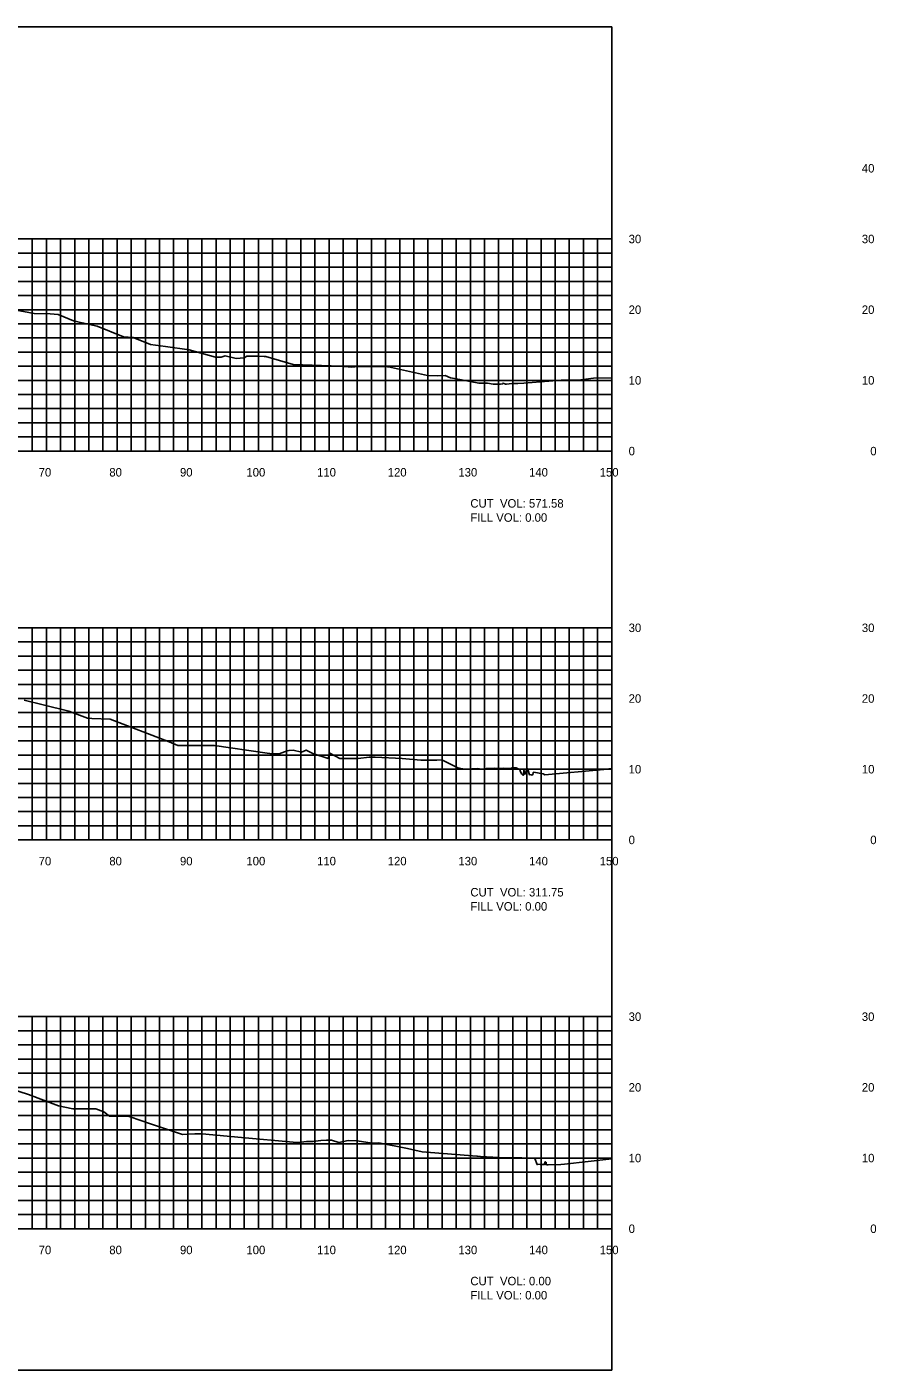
# Model space of a CAD drawing. Extents: x 1800976 to 1805104, y 250057 to 250580.
# Drawn here: x 1802358.2 to 1802478.4, y 250079.4 to 250269.4 of the extents above; entities that cross this region are included whole.
import ezdxf

# ---------------------------------------------------------------- set-up
doc = ezdxf.new("R2010")
doc.units = 0
for name, color, linetype in [('10', 7, 'Continuous'), ('31', 7, 'Continuous'), ('60', 7, 'Continuous'), ('ANNO-TXT', 7, 'Continuous'), ('Level 62', 7, 'Continuous'), ('M-ROADS', 7, 'Continuous')]:
    doc.layers.add(name, color=color, linetype=linetype)

msp = doc.modelspace()

# ---------------------------------------------------------------- linework, layer by layer
msp.add_lwpolyline([(1802141, 250079.43), (1802441, 250079.43), (1802441, 250269.43), (1802141, 250269.43)], close=True)
at = {"layer": '60'}
for p, q in [((1802441, 250209.43), (1802441, 250239.43)), ((1802441.06, 250239.43), (1802441, 250239.43)), ((1802441.06, 250229.43), (1802441, 250229.43)), ((1802441.06, 250219.43), (1802441, 250219.43)), ((1802141, 250209.43), (1802441, 250209.43)), ((1802361, 250209.37), (1802361, 250209.43)), ((1802371, 250209.37), (1802371, 250209.43)), ((1802381, 250209.37), (1802381, 250209.43)), ((1802391, 250209.37), (1802391, 250209.43)), ((1802401, 250209.37), (1802401, 250209.43)), ((1802411, 250209.37), (1802411, 250209.43)), ((1802421, 250209.37), (1802421, 250209.43)), ((1802431, 250209.37), (1802431, 250209.43)), ((1802441, 250209.37), (1802441, 250209.43)), ((1802441.06, 250209.43), (1802441, 250209.43)), ((1802441, 250154.43), (1802441, 250184.43)), ((1802441.06, 250184.43), (1802441, 250184.43)), ((1802441.06, 250174.43), (1802441, 250174.43)), ((1802441.06, 250164.43), (1802441, 250164.43)), ((1802141, 250154.43), (1802441, 250154.43)), ((1802361, 250154.37), (1802361, 250154.43)), ((1802371, 250154.37), (1802371, 250154.43)), ((1802381, 250154.37), (1802381, 250154.43)), ((1802391, 250154.37), (1802391, 250154.43)), ((1802401, 250154.37), (1802401, 250154.43)), ((1802411, 250154.37), (1802411, 250154.43)), ((1802421, 250154.37), (1802421, 250154.43)), ((1802431, 250154.37), (1802431, 250154.43)), ((1802441, 250154.37), (1802441, 250154.43)), ((1802441.06, 250154.43), (1802441, 250154.43)), ((1802441, 250099.43), (1802441, 250129.43)), ((1802441.06, 250129.43), (1802441, 250129.43)), ((1802441.06, 250119.43), (1802441, 250119.43)), ((1802441.06, 250109.43), (1802441, 250109.43)), ((1802141, 250099.43), (1802441, 250099.43)), ((1802361, 250099.37), (1802361, 250099.43)), ((1802371, 250099.37), (1802371, 250099.43)), ((1802381, 250099.37), (1802381, 250099.43)), ((1802391, 250099.37), (1802391, 250099.43)), ((1802401, 250099.37), (1802401, 250099.43)), ((1802411, 250099.37), (1802411, 250099.43)), ((1802421, 250099.37), (1802421, 250099.43)), ((1802431, 250099.37), (1802431, 250099.43)), ((1802441, 250099.37), (1802441, 250099.43)), ((1802441.06, 250099.43), (1802441, 250099.43))]:
    msp.add_line(p, q, dxfattribs=at)
at = {"layer": 'Level 62'}
for p, q in [((1802141, 250239.43), (1802441, 250239.43)), ((1802359, 250209.43), (1802359, 250239.43)), ((1802361, 250209.43), (1802361, 250239.43)), ((1802363, 250209.43), (1802363, 250239.43)), ((1802365, 250209.43), (1802365, 250239.43)), ((1802367, 250209.43), (1802367, 250239.43)), ((1802369, 250209.43), (1802369, 250239.43)), ((1802371, 250209.43), (1802371, 250239.43)), ((1802373, 250209.43), (1802373, 250239.43)), ((1802375, 250209.43), (1802375, 250239.43)), ((1802377, 250209.43), (1802377, 250239.43)), ((1802379, 250209.43), (1802379, 250239.43)), ((1802381, 250209.43), (1802381, 250239.43)), ((1802383, 250209.43), (1802383, 250239.43)), ((1802385, 250209.43), (1802385, 250239.43)), ((1802387, 250209.43), (1802387, 250239.43)), ((1802389, 250209.43), (1802389, 250239.43)), ((1802391, 250209.43), (1802391, 250239.43)), ((1802393, 250209.43), (1802393, 250239.43)), ((1802395, 250209.43), (1802395, 250239.43)), ((1802397, 250209.43), (1802397, 250239.43)), ((1802399, 250209.43), (1802399, 250239.43)), ((1802401, 250209.43), (1802401, 250239.43)), ((1802403, 250209.43), (1802403, 250239.43)), ((1802405, 250209.43), (1802405, 250239.43)), ((1802407, 250209.43), (1802407, 250239.43)), ((1802409, 250209.43), (1802409, 250239.43)), ((1802411, 250209.43), (1802411, 250239.43)), ((1802413, 250209.43), (1802413, 250239.43)), ((1802415, 250209.43), (1802415, 250239.43)), ((1802417, 250209.43), (1802417, 250239.43)), ((1802419, 250209.43), (1802419, 250239.43)), ((1802421, 250209.43), (1802421, 250239.43)), ((1802423, 250209.43), (1802423, 250239.43)), ((1802425, 250209.43), (1802425, 250239.43)), ((1802427, 250209.43), (1802427, 250239.43)), ((1802429, 250209.43), (1802429, 250239.43)), ((1802431, 250209.43), (1802431, 250239.43)), ((1802433, 250209.43), (1802433, 250239.43)), ((1802435, 250209.43), (1802435, 250239.43)), ((1802437, 250209.43), (1802437, 250239.43)), ((1802439, 250209.43), (1802439, 250239.43)), ((1802441, 250209.43), (1802441, 250239.43)), ((1802141, 250237.43), (1802441, 250237.43)), ((1802141, 250235.43), (1802441, 250235.43)), ((1802141, 250233.43), (1802441, 250233.43)), ((1802141, 250231.43), (1802441, 250231.43)), ((1802141, 250229.43), (1802441, 250229.43)), ((1802141, 250227.43), (1802441, 250227.43)), ((1802141, 250225.43), (1802441, 250225.43)), ((1802141, 250223.43), (1802441, 250223.43)), ((1802141, 250221.43), (1802441, 250221.43)), ((1802141, 250219.43), (1802441, 250219.43)), ((1802141, 250217.43), (1802441, 250217.43)), ((1802141, 250215.43), (1802441, 250215.43)), ((1802141, 250213.43), (1802441, 250213.43)), ((1802141, 250211.43), (1802441, 250211.43)), ((1802141, 250209.43), (1802441, 250209.43)), ((1802141, 250184.43), (1802441, 250184.43)), ((1802359, 250154.43), (1802359, 250184.43)), ((1802361, 250154.43), (1802361, 250184.43)), ((1802363, 250154.43), (1802363, 250184.43)), ((1802365, 250154.43), (1802365, 250184.43)), ((1802367, 250154.43), (1802367, 250184.43)), ((1802369, 250154.43), (1802369, 250184.43)), ((1802371, 250154.43), (1802371, 250184.43)), ((1802373, 250154.43), (1802373, 250184.43)), ((1802375, 250154.43), (1802375, 250184.43)), ((1802377, 250154.43), (1802377, 250184.43)), ((1802379, 250154.43), (1802379, 250184.43)), ((1802381, 250154.43), (1802381, 250184.43)), ((1802383, 250154.43), (1802383, 250184.43)), ((1802385, 250154.43), (1802385, 250184.43)), ((1802387, 250154.43), (1802387, 250184.43)), ((1802389, 250154.43), (1802389, 250184.43)), ((1802391, 250154.43), (1802391, 250184.43)), ((1802393, 250154.43), (1802393, 250184.43)), ((1802395, 250154.43), (1802395, 250184.43)), ((1802397, 250154.43), (1802397, 250184.43)), ((1802399, 250154.43), (1802399, 250184.43)), ((1802401, 250154.43), (1802401, 250184.43)), ((1802403, 250154.43), (1802403, 250184.43)), ((1802405, 250154.43), (1802405, 250184.43)), ((1802407, 250154.43), (1802407, 250184.43)), ((1802409, 250154.43), (1802409, 250184.43)), ((1802411, 250154.43), (1802411, 250184.43)), ((1802413, 250154.43), (1802413, 250184.43)), ((1802415, 250154.43), (1802415, 250184.43)), ((1802417, 250154.43), (1802417, 250184.43)), ((1802419, 250154.43), (1802419, 250184.43)), ((1802421, 250154.43), (1802421, 250184.43)), ((1802423, 250154.43), (1802423, 250184.43)), ((1802425, 250154.43), (1802425, 250184.43)), ((1802427, 250154.43), (1802427, 250184.43)), ((1802429, 250154.43), (1802429, 250184.43)), ((1802431, 250154.43), (1802431, 250184.43)), ((1802433, 250154.43), (1802433, 250184.43)), ((1802435, 250154.43), (1802435, 250184.43)), ((1802437, 250154.43), (1802437, 250184.43)), ((1802439, 250154.43), (1802439, 250184.43)), ((1802441, 250154.43), (1802441, 250184.43)), ((1802141, 250182.43), (1802441, 250182.43)), ((1802141, 250180.43), (1802441, 250180.43)), ((1802141, 250178.43), (1802441, 250178.43)), ((1802141, 250176.43), (1802441, 250176.43)), ((1802141, 250174.43), (1802441, 250174.43)), ((1802141, 250172.43), (1802441, 250172.43)), ((1802141, 250170.43), (1802441, 250170.43)), ((1802141, 250168.43), (1802441, 250168.43)), ((1802141, 250166.43), (1802441, 250166.43)), ((1802141, 250164.43), (1802441, 250164.43)), ((1802141, 250162.43), (1802441, 250162.43)), ((1802141, 250160.43), (1802441, 250160.43)), ((1802141, 250158.43), (1802441, 250158.43)), ((1802141, 250156.43), (1802441, 250156.43)), ((1802141, 250154.43), (1802441, 250154.43)), ((1802141, 250129.43), (1802441, 250129.43)), ((1802359, 250099.43), (1802359, 250129.43)), ((1802361, 250099.43), (1802361, 250129.43)), ((1802363, 250099.43), (1802363, 250129.43)), ((1802365, 250099.43), (1802365, 250129.43)), ((1802367, 250099.43), (1802367, 250129.43)), ((1802369, 250099.43), (1802369, 250129.43)), ((1802371, 250099.43), (1802371, 250129.43)), ((1802373, 250099.43), (1802373, 250129.43)), ((1802375, 250099.43), (1802375, 250129.43)), ((1802377, 250099.43), (1802377, 250129.43)), ((1802379, 250099.43), (1802379, 250129.43)), ((1802381, 250099.43), (1802381, 250129.43)), ((1802383, 250099.43), (1802383, 250129.43)), ((1802385, 250099.43), (1802385, 250129.43)), ((1802387, 250099.43), (1802387, 250129.43)), ((1802389, 250099.43), (1802389, 250129.43)), ((1802391, 250099.43), (1802391, 250129.43)), ((1802393, 250099.43), (1802393, 250129.43)), ((1802395, 250099.43), (1802395, 250129.43)), ((1802397, 250099.43), (1802397, 250129.43)), ((1802399, 250099.43), (1802399, 250129.43)), ((1802401, 250099.43), (1802401, 250129.43)), ((1802403, 250099.43), (1802403, 250129.43)), ((1802405, 250099.43), (1802405, 250129.43)), ((1802407, 250099.43), (1802407, 250129.43)), ((1802409, 250099.43), (1802409, 250129.43)), ((1802411, 250099.43), (1802411, 250129.43)), ((1802413, 250099.43), (1802413, 250129.43)), ((1802415, 250099.43), (1802415, 250129.43)), ((1802417, 250099.43), (1802417, 250129.43)), ((1802419, 250099.43), (1802419, 250129.43)), ((1802421, 250099.43), (1802421, 250129.43)), ((1802423, 250099.43), (1802423, 250129.43)), ((1802425, 250099.43), (1802425, 250129.43)), ((1802427, 250099.43), (1802427, 250129.43)), ((1802429, 250099.43), (1802429, 250129.43)), ((1802431, 250099.43), (1802431, 250129.43)), ((1802433, 250099.43), (1802433, 250129.43)), ((1802435, 250099.43), (1802435, 250129.43)), ((1802437, 250099.43), (1802437, 250129.43)), ((1802439, 250099.43), (1802439, 250129.43)), ((1802441, 250099.43), (1802441, 250129.43)), ((1802141, 250127.43), (1802441, 250127.43)), ((1802141, 250125.43), (1802441, 250125.43)), ((1802141, 250123.43), (1802441, 250123.43)), ((1802141, 250121.43), (1802441, 250121.43)), ((1802141, 250119.43), (1802441, 250119.43)), ((1802141, 250117.43), (1802441, 250117.43)), ((1802141, 250115.43), (1802441, 250115.43)), ((1802141, 250113.43), (1802441, 250113.43)), ((1802141, 250111.43), (1802441, 250111.43)), ((1802141, 250109.43), (1802441, 250109.43)), ((1802141, 250107.43), (1802441, 250107.43)), ((1802141, 250105.43), (1802441, 250105.43)), ((1802141, 250103.43), (1802441, 250103.43)), ((1802141, 250101.43), (1802441, 250101.43)), ((1802141, 250099.43), (1802441, 250099.43))]:
    msp.add_line(p, q, dxfattribs=at)
at = {"layer": 'M-ROADS'}
for points in [[(1802344.77, 250231.59), (1802359.28, 250228.9), (1802361.52, 250228.82), (1802362.66, 250228.77), (1802364.81, 250227.83), (1802366.25, 250227.53), (1802368.19, 250227.12), (1802371.89, 250225.59), (1802373.26, 250225.5), (1802375.72, 250224.51), (1802377.84, 250224.23), (1802381.19, 250223.77), (1802384.92, 250222.73), (1802385.71, 250222.73), (1802386.3, 250222.88), (1802387.87, 250222.54), (1802388.97, 250222.64), (1802389.34, 250222.85), (1802391.06, 250222.85), (1802391.8, 250222.8), (1802392.05, 250222.81), (1802395.91, 250221.68), (1802402.62, 250221.44), (1802404.22, 250221.3), (1802405.13, 250221.41), (1802406.46, 250221.41), (1802408.57, 250221.41), (1802408.99, 250221.37), (1802409.18, 250221.37), (1802409.32, 250221.35), (1802409.4, 250221.34), (1802414.92, 250220.12), (1802416.38, 250220.09), (1802417.44, 250220.13), (1802418.19, 250219.8), (1802418.76, 250219.68), (1802422.22, 250219.04), (1802423.43, 250219.02), (1802424.23, 250218.88), (1802424.6, 250218.88), (1802424.96, 250218.88), (1802425.25, 250218.88), (1802425.59, 250218.93), (1802425.64, 250219.04), (1802425.98, 250218.91), (1802426.13, 250218.87), (1802426.89, 250218.99), (1802427.7, 250218.99), (1802428.57, 250219.02), (1802433.27, 250219.41), (1802433.86, 250219.45), (1802436.65, 250219.49), (1802438.41, 250219.76), (1802441, 250219.79)], [(1802357.86, 250174.2), (1802360.54, 250173.53), (1802364.17, 250172.62), (1802366.8, 250171.64), (1802367.43, 250171.61), (1802370.04, 250171.5), (1802378.35, 250168.29), (1802379.61, 250167.78), (1802380.48, 250167.79), (1802381.99, 250167.79), (1802384.38, 250167.79), (1802384.51, 250167.79), (1802384.57, 250167.79), (1802384.78, 250167.77), (1802391.92, 250166.75), (1802392.93, 250166.61), (1802393.96, 250166.61), (1802395.06, 250167.01), (1802395.35, 250167.1), (1802395.92, 250167.11), (1802397.1, 250166.86), (1802397.76, 250167.13), (1802398.71, 250166.63), (1802400.86, 250165.95), (1802401.13, 250166.7), (1802402.54, 250165.95), (1802404.78, 250165.95), (1802405.1, 250165.96), (1802406.7, 250166.14), (1802407.04, 250166.12), (1802407.54, 250166.12), (1802411.36, 250165.94), (1802413.99, 250165.72), (1802416.13, 250165.69), (1802416.23, 250165.69), (1802416.94, 250165.75), (1802419.31, 250164.57), (1802419.42, 250164.59), (1802419.94, 250164.47), (1802420.31, 250164.44), (1802420.41, 250164.45), (1802421.98, 250164.51), (1802422.66, 250164.46), (1802422.85, 250164.44), (1802423.22, 250164.51), (1802424.42, 250164.6), (1802424.93, 250164.55), (1802425.68, 250164.57), (1802426.32, 250164.51), (1802426.84, 250164.6), (1802426.91, 250164.62), (1802427.49, 250164.64), (1802428.05, 250164.36), (1802428.07, 250164.22), (1802428.25, 250163.76), (1802428.42, 250163.59), (1802428.5, 250163.57), (1802428.56, 250164.41), (1802428.71, 250163.71), (1802428.76, 250163.77), (1802429.05, 250164.54), (1802429.17, 250164.24), (1802429.36, 250163.63), (1802429.43, 250163.66), (1802429.61, 250163.65), (1802429.71, 250163.61), (1802429.78, 250163.66), (1802429.83, 250163.62), (1802429.87, 250163.96), (1802429.94, 250163.99), (1802431.32, 250163.76), (1802431.52, 250163.63), (1802439.87, 250164.41), (1802440.99, 250164.52), (1802441, 250164.52)], [(1802353.12, 250120.11), (1802358.45, 250118.41), (1802362.69, 250116.83), (1802364.76, 250116.4), (1802366.03, 250116.4), (1802367.98, 250116.4), (1802369.14, 250115.97), (1802369.92, 250115.35), (1802370.78, 250115.35), (1802372.71, 250115.32), (1802376.02, 250114.19), (1802380.26, 250112.78), (1802382.01, 250112.85), (1802382.63, 250112.85), (1802383.03, 250112.85), (1802388.63, 250112.35), (1802395.91, 250111.7), (1802396.73, 250111.63), (1802397.82, 250111.77), (1802398.75, 250111.77), (1802399.82, 250111.89), (1802400.63, 250111.97), (1802401.35, 250111.97), (1802402.4, 250111.61), (1802403.7, 250111.91), (1802404.96, 250111.88), (1802407.11, 250111.53), (1802408.05, 250111.58), (1802412.1, 250110.79), (1802414.18, 250110.32), (1802421.9, 250109.71), (1802422.03, 250109.71), (1802422.42, 250109.67), (1802425.92, 250109.47), (1802426.86, 250109.47), (1802428.29, 250109.47), (1802429.87, 250109.42), (1802430.1, 250109.35), (1802430.12, 250109.37), (1802430.12, 250109.38), (1802430.13, 250109.37), (1802430.45, 250108.52), (1802430.45, 250108.51), (1802430.45, 250108.52), (1802430.45, 250108.51), (1802430.47, 250108.53), (1802430.49, 250108.52), (1802430.52, 250108.57), (1802430.87, 250108.52), (1802431.28, 250108.52), (1802431.45, 250108.51), (1802431.59, 250108.9), (1802431.63, 250108.49), (1802431.69, 250108.66), (1802431.72, 250108.83), (1802431.72, 250108.53), (1802431.77, 250108.53), (1802431.85, 250108.48), (1802431.99, 250108.47), (1802433.81, 250108.51), (1802434.33, 250108.58), (1802441, 250109.33)]]:
    msp.add_lwpolyline(points, dxfattribs=at)

# ---------------------------------------------------------------- texts
at = {"layer": '10'}
for s, p in [('70', (1802359.9, 250205.83)), ('80', (1802369.9, 250205.83)), ('90', (1802379.9, 250205.83)), ('100', (1802389.3, 250205.83)), ('110', (1802399.3, 250205.83)), ('120', (1802409.3, 250205.83)), ('130', (1802419.3, 250205.83)), ('140', (1802429.3, 250205.83)), ('150', (1802439.3, 250205.83)), ('70', (1802359.9, 250150.83)), ('80', (1802369.9, 250150.83)), ('90', (1802379.9, 250150.83)), ('100', (1802389.3, 250150.83)), ('110', (1802399.3, 250150.83)), ('120', (1802409.3, 250150.83)), ('130', (1802419.3, 250150.83)), ('140', (1802429.3, 250150.83)), ('150', (1802439.3, 250150.83)), ('70', (1802359.9, 250095.83)), ('80', (1802369.9, 250095.83)), ('90', (1802379.9, 250095.83)), ('100', (1802389.3, 250095.83)), ('110', (1802399.3, 250095.83)), ('120', (1802409.3, 250095.83)), ('130', (1802419.3, 250095.83)), ('140', (1802429.3, 250095.83)), ('150', (1802439.3, 250095.83))]:
    msp.add_text(s, height=1.2, dxfattribs=at).set_placement(p)
at = {"layer": '31'}
for s, p in [('40', (1802476.4, 250248.83)), ('30', (1802443.4, 250238.83)), ('30', (1802476.4, 250238.83)), ('20', (1802443.4, 250228.83)), ('20', (1802476.4, 250228.83)), ('10', (1802443.4, 250218.83)), ('10', (1802476.4, 250218.83)), ('0', (1802443.4, 250208.83)), ('0', (1802477.6, 250208.83)), ('30', (1802443.4, 250183.83)), ('30', (1802476.4, 250183.83)), ('20', (1802443.4, 250173.83)), ('20', (1802476.4, 250173.83)), ('10', (1802443.4, 250163.83)), ('10', (1802476.4, 250163.83)), ('0', (1802443.4, 250153.83)), ('0', (1802477.6, 250153.83)), ('30', (1802443.4, 250128.83)), ('30', (1802476.4, 250128.83)), ('20', (1802443.4, 250118.83)), ('20', (1802476.4, 250118.83)), ('10', (1802443.4, 250108.83)), ('10', (1802476.4, 250108.83)), ('0', (1802443.4, 250098.83)), ('0', (1802477.6, 250098.83))]:
    msp.add_text(s, height=1.2, dxfattribs=at).set_placement(p)
at = {"layer": 'ANNO-TXT'}
for s, p in [('CUT  VOL: 571.58', (1802421, 250201.43)), ('FILL VOL: 0.00', (1802421, 250199.43)), ('CUT  VOL: 311.75', (1802421, 250146.43)), ('FILL VOL: 0.00', (1802421, 250144.43)), ('CUT  VOL: 0.00', (1802421, 250091.43)), ('FILL VOL: 0.00', (1802421, 250089.43))]:
    msp.add_text(s, height=1.2, dxfattribs=at).set_placement(p)

doc.saveas('drawing.dxf')
